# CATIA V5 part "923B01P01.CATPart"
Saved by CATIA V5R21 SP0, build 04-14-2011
Part number: 923B01P01
Bounding box of the stored display mesh (mm): x -17.1 to 17.1, y -76.2 to 76.2, z -4.4 to 4.4
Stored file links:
  C:\Users\ALI OZGUN\Desktop\alhan\923B01P01.CATPart
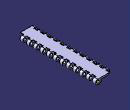
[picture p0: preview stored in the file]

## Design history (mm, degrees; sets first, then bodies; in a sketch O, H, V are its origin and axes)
Body1 (main body)
  Sketch1 on zx-plane, origin (0, 0, 0), H (-1, 0, 0), V (0, 0, 1)
    construction line L1 (-12.7, 0) -> (12.7, 0)
    point P1 (-12.7, 0)
    line L2 (-12.7, 4.4) -> (12.7, 4.4)
    line L3 (12.7, -4.4) -> (-12.7, -4.4)
    arc A1 centre (12.7, 0) radius 4.4 from (12.7, 4.4) to (12.7, -4.4) cw
    arc A2 centre (-12.7, 0) radius 4.4 from (-12.7, -4.4) to (-12.7, 4.4) cw
    distance L1 L2 = 4.4
    length L1 = 25.4
    distance P1 V = 12.7
    coincidence: P1 H
    horizontal: L1 H
    tangency: A1 L2, A2 L2, A1 L3, A2 L3
  Pad1: profile Sketch1, direction (0, 1, 0), length 76.2, mirrored extent
  Sketch2 on face of Pad1 from Sketch1.L2, origin (0, 0, 4.4), H (1, 0, 0), V (0, 1, 0)
    line L1 (-22.3127, -63.5) -> (-9.75, -63.5)
    line L2 (-9.75, -63.5) -> (-9.75, -70.6)
    line L3 (-9.75, -70.6) -> (-22.3127, -70.6)
    line L4 (-22.3127, -70.6) -> (-22.3127, -63.5)
    line L5 (24.6678, -76.95) -> (9.75, -76.95)
    line L6 (9.75, -76.95) -> (9.75, -69.85)
    line L7 (9.75, -69.85) -> (24.6678, -69.85)
    line L8 (24.6678, -69.85) -> (24.6678, -76.95)
    reference projected line E1 (-12.7, -76.2) -> (12.7, -76.2) from edge [start face of Pad1 | face of Pad1 from Sketch1.L2]
    reference projected line E2 (-12.7, -76.2) -> (12.7, -76.2) from edge [start face of Pad1 | face of Pad1 from Sketch1.L2]
    distance L3 E1 = 5.6
    length L4 = 7.1
    distance L7 L5 = 7.1
    distance L5 E2 = 0.75
    distance L2 L6 = 19.5
    distance L2 V = 9.75
    horizontal: L1 H, L3 H, L5 H, L7 H
    vertical: L2 V, L4 V, L6 V, L8 V
  Pocket1: profile Sketch2, direction (0, 0, -1), length 76.2
  RectPattern1: of Pocket1, direction 1 instances 12, spacing 12.7, along axis of face of Pad1 from Sketch1.A2
  Sketch3 on face of Pad1 from Sketch1.L3, origin (0, 0, -4.4), H (1, 0, 0), V (0, -1, 0)
    line L1 (-7, 90.4553) -> (7, 90.4553)
    line L2 (7, 90.4553) -> (7, -88.0088)
    line L3 (7, -88.0088) -> (-7, -88.0088)
    line L4 (-7, -88.0088) -> (-7, 90.4553)
    length L1 = 14
    distance L4 V = 7
    horizontal: L1 H, L3 H
    vertical: L2 V, L4 V
  Pocket2: profile Sketch3, direction (0, 0, 1), length 5.8
  Fillet1: radius 2, on edge [face of Pad1 from Sketch1.L3 | face of Pocket2 from Sketch3.L2]; edge [face of Pad1 from Sketch1.L3 | face of Pocket2 from Sketch3.L4]
  Sketch4 on yz-plane, origin (0, 0, 0), H (0, 1, 0), V (0, 0, 1)
    point P3 (69.85, -4.4)
    point P5 (69.85, -4.4)
    point P7 (57.15, -4.4)
    point P9 (57.15, -4.4)
    point P11 (44.45, -4.4)
    point P13 (44.45, -4.4)
    point P15 (31.75, -4.4)
    point P16 (31.75, -4.4)
    point P18 (19.05, -4.4)
    point P19 (19.05, 1.4)
    point P20 (19.05, -4.4)
    line L1 (-76.2, -4.4) -> (-76.2, 1.4)
    line L2 (-69.85, 1.4) -> (-69.85, -4.4)
    line L3 (-69.85, -4.4) -> (-76.2, -4.4)
    line L4 (-57.15, -4.4) -> (-64.25, -4.4)
    line L5 (-64.25, -4.4) -> (-64.25, 1.4)
    line L6 (-57.15, 1.4) -> (-57.15, -4.4)
    line L7 (-44.45, -4.4) -> (-51.55, -4.4)
    line L8 (-51.55, -4.4) -> (-51.55, 1.4)
    line L9 (-44.45, 1.4) -> (-44.45, -4.4)
    line L10 (-31.75, -4.4) -> (-38.85, -4.4)
    line L11 (-38.85, -4.4) -> (-38.85, 1.4)
    line L12 (-19.05, -4.4) -> (-26.15, -4.4)
    line L13 (-26.15, -4.4) -> (-26.15, 1.4)
    line L14 (-19.05, 1.4) -> (-19.05, -4.4)
    line L15 (-6.35, -4.4) -> (-13.45, -4.4)
    line L16 (-13.45, -4.4) -> (-13.45, 1.4)
    line L17 (-6.35, 1.4) -> (-6.35, -4.4)
    line L18 (6.35, -4.4) -> (-0.75, -4.4)
    line L19 (-0.75, -4.4) -> (-0.75, 1.4)
    line L20 (6.35, 1.4) -> (6.35, -4.4)
    construction line L21 (19.05, -4.4) -> (11.95, -4.4)
    construction line L22 (11.95, -4.4) -> (11.95, 4.4)
    construction line L23 (11.95, 4.4) -> (19.05, 4.4)
    construction line L24 (19.05, 4.4) -> (19.05, -4.4)
    line L25 (19.05, 1.4) -> (19.05, -4.4)
    line L26 (19.05, -4.4) -> (11.95, -4.4)
    line L27 (11.95, -4.4) -> (11.95, 1.4)
    construction line L28 (31.75, -4.4) -> (24.65, -4.4)
    construction line L29 (24.65, -4.4) -> (24.65, 4.4)
    construction line L30 (24.65, 4.4) -> (31.75, 4.4)
    construction line L31 (31.75, 4.4) -> (31.75, -4.4)
    line L32 (31.75, -4.4) -> (24.65, -4.4)
    line L33 (24.65, -4.4) -> (24.65, 1.4)
    line L34 (31.75, 1.4) -> (31.75, -4.4)
    construction line L35 (44.45, -4.4) -> (37.35, -4.4)
    construction line L36 (37.35, -4.4) -> (37.35, 4.4)
    construction line L37 (37.35, 4.4) -> (44.45, 4.4)
    construction line L38 (44.45, 4.4) -> (44.45, -4.4)
    line L39 (44.45, -4.4) -> (37.35, -4.4)
    line L40 (37.35, -4.4) -> (37.35, 1.4)
    line L41 (44.45, 1.4) -> (44.45, -4.4)
    construction line L42 (57.15, -4.4) -> (50.05, -4.4)
    construction line L43 (50.05, -4.4) -> (50.05, 4.4)
    construction line L44 (50.05, 4.4) -> (57.15, 4.4)
    construction line L45 (57.15, 4.4) -> (57.15, -4.4)
    line L46 (57.15, -4.4) -> (50.05, -4.4)
    line L47 (50.05, -4.4) -> (50.05, 1.4)
    line L48 (57.15, 1.4) -> (57.15, -4.4)
    construction line L49 (69.85, -4.4) -> (62.75, -4.4)
    construction line L50 (62.75, -4.4) -> (62.75, 4.4)
    construction line L51 (62.75, 4.4) -> (69.85, 4.4)
    construction line L52 (69.85, 4.4) -> (69.85, -4.4)
    line L53 (69.85, 1.4) -> (69.85, -4.4)
    line L54 (69.85, -4.4) -> (62.75, -4.4)
    line L55 (62.75, -4.4) -> (62.75, 1.4)
    construction line L56 (-76.2, 1.4) -> (76.2, 1.4)
    line L57 (62.75, 1.4) -> (69.85, 1.4)
    line L58 (50.05, 1.4) -> (57.15, 1.4)
    line L59 (37.35, 1.4) -> (44.45, 1.4)
    line L60 (-76.2, 1.4) -> (-69.85, 1.4)
    point P60 (19.05, 1.4)
    line L61 (24.65, 1.4) -> (31.75, 1.4)
    point P61 (24.65, 1.4)
    point P62 (24.65, 1.4)
    point P63 (11.95, 1.4)
    point P64 (6.35, 1.4)
    point P65 (-0.75, 1.4)
    point P66 (-6.35, 1.4)
    point P67 (-13.45, 1.4)
    point P68 (-19.05, 1.4)
    point P69 (-26.15, 1.4)
    point P70 (-38.85, 1.4)
    point P71 (-44.45, 1.4)
    point P72 (-51.55, 1.4)
    point P73 (-57.15, 1.4)
    point P74 (-64.25, 1.4)
    point P75 (-69.85, 1.4)
    line L62 (-64.25, 1.4) -> (-57.15, 1.4)
    line L63 (-51.55, 1.4) -> (-44.45, 1.4)
    line L64 (-38.85, 1.4) -> (-31.75, 1.4)
    line L65 (-26.15, 1.4) -> (-19.05, 1.4)
    line L66 (-13.45, 1.4) -> (-6.35, 1.4)
    line L67 (-0.75, 1.4) -> (6.35, 1.4)
    line L68 (11.95, 1.4) -> (19.05, 1.4)
    line L69 (-31.75, 1.4) -> (-31.75, -4.4)
    coincidence: L24 P60, L29 P61, L60 L61, L56 P62, L56 P63, L56 P64, L56 P65, L56 P66, L56 P67, L56 P68, L56 P69, L56 P70, L56 P71, L56 P72, L56 P73, L56 P74, L56 P75, L60 L62, L62 L63, L63 L64, L64 L65, L65 L66, L66 L67, L67 L68, P3 P5, P7 P9, P11 P13, P15 P16, P18 P20, P19 P60, P61 P62
    vertical: L69 V
  Pocket3: profile Sketch4, direction (1, 0, 0), length 27.8
  Sketch5 on yz-plane, origin (0, 0, 0), H (0, 1, 0), V (0, 0, 1)
    line L1 (-63.5, -4.4) -> (-70.6, -4.4)
    point P1 (-63.5, -4.4)
    point P2 (-70.6, -4.4)
    line L2 (-63.5, 1.4) -> (-63.5, -4.4)
    point P3 (-63.5, 1.4)
    point P4 (-63.5, -4.4)
    line L3 (-70.6, 1.4) -> (-63.5, 1.4)
    point P5 (-70.6, 1.4)
    point P6 (-63.5, 1.4)
    line L4 (-70.6, -4.4) -> (-70.6, 1.4)
    point P7 (-70.6, -4.4)
    point P8 (-70.6, 1.4)
    line L5 (-50.8, 1.4) -> (-50.8, -4.4)
    point P9 (-50.8, 1.4)
    point P10 (-50.8, -4.4)
    line L6 (-57.9, 1.4) -> (-50.8, 1.4)
    point P11 (-57.9, 1.4)
    point P12 (-50.8, 1.4)
    line L7 (-57.9, -4.4) -> (-57.9, 1.4)
    point P13 (-57.9, -4.4)
    point P14 (-57.9, 1.4)
    line L8 (-50.8, -4.4) -> (-57.9, -4.4)
    point P15 (-50.8, -4.4)
    point P16 (-57.9, -4.4)
    line L9 (-38.1, 1.4) -> (-38.1, -4.4)
    point P17 (-38.1, 1.4)
    point P18 (-38.1, -4.4)
    line L10 (-45.2, 1.4) -> (-38.1, 1.4)
    point P19 (-45.2, 1.4)
    point P20 (-38.1, 1.4)
    line L11 (-45.2, -4.4) -> (-45.2, 1.4)
    point P21 (-45.2, -4.4)
    point P22 (-45.2, 1.4)
    line L12 (-38.1, -4.4) -> (-45.2, -4.4)
    point P23 (-38.1, -4.4)
    point P24 (-45.2, -4.4)
    line L13 (-25.4, 1.4) -> (-25.4, -4.4)
    point P25 (-25.4, 1.4)
    point P26 (-25.4, -4.4)
    line L14 (-32.5, 1.4) -> (-25.4, 1.4)
    point P27 (-32.5, 1.4)
    point P28 (-25.4, 1.4)
    line L15 (-32.5, -4.4) -> (-32.5, 1.4)
    point P29 (-32.5, -4.4)
    point P30 (-32.5, 1.4)
    line L16 (-25.4, -4.4) -> (-32.5, -4.4)
    point P31 (-25.4, -4.4)
    point P32 (-32.5, -4.4)
    line L17 (-12.7, 1.4) -> (-12.7, -4.4)
    point P33 (-12.7, 1.4)
    point P34 (-12.7, -4.4)
    line L18 (-19.8, 1.4) -> (-12.7, 1.4)
    point P35 (-19.8, 1.4)
    point P36 (-12.7, 1.4)
    line L19 (-19.8, -4.4) -> (-19.8, 1.4)
    point P37 (-19.8, -4.4)
    point P38 (-19.8, 1.4)
    line L20 (-12.7, -4.4) -> (-19.8, -4.4)
    point P39 (-12.7, -4.4)
    point P40 (-19.8, -4.4)
    line L21 (0, 1.4) -> (0, -4.4)
    point P41 (0, 1.4)
    point P42 (0, -4.4)
    line L22 (-7.1, 1.4) -> (0, 1.4)
    point P43 (-7.1, 1.4)
    point P44 (0, 1.4)
    line L23 (-7.1, -4.4) -> (-7.1, 1.4)
    point P45 (-7.1, -4.4)
    point P46 (-7.1, 1.4)
    line L24 (0, -4.4) -> (-7.1, -4.4)
    point P47 (0, -4.4)
    point P48 (-7.1, -4.4)
    line L25 (12.7, 1.4) -> (12.7, -4.4)
    point P49 (12.7, 1.4)
    point P50 (12.7, -4.4)
    line L26 (5.6, 1.4) -> (12.7, 1.4)
    point P51 (5.6, 1.4)
    point P52 (12.7, 1.4)
    line L27 (5.6, -4.4) -> (5.6, 1.4)
    point P53 (5.6, -4.4)
    point P54 (5.6, 1.4)
    line L28 (12.7, -4.4) -> (5.6, -4.4)
    point P55 (12.7, -4.4)
    point P56 (5.6, -4.4)
    line L29 (18.3, 1.4) -> (25.4, 1.4)
    point P57 (18.3, 1.4)
    point P58 (25.4, 1.4)
    line L30 (18.3, -4.4) -> (18.3, 1.4)
    point P59 (18.3, -4.4)
    point P60 (18.3, 1.4)
    line L31 (25.4, -4.4) -> (18.3, -4.4)
    point P61 (25.4, -4.4)
    point P62 (18.3, -4.4)
    line L32 (25.4, 1.4) -> (25.4, -4.4)
    point P63 (25.4, 1.4)
    point P64 (25.4, -4.4)
    line L33 (38.1, 1.4) -> (38.1, -4.4)
    point P65 (38.1, 1.4)
    point P66 (38.1, -4.4)
    line L34 (31, 1.4) -> (38.1, 1.4)
    point P67 (31, 1.4)
    point P68 (38.1, 1.4)
    line L35 (31, -4.4) -> (31, 1.4)
    point P69 (31, -4.4)
    point P70 (31, 1.4)
    line L36 (38.1, -4.4) -> (31, -4.4)
    point P71 (38.1, -4.4)
    point P72 (31, -4.4)
    line L37 (50.8, 1.4) -> (50.8, -4.4)
    point P73 (50.8, 1.4)
    point P74 (50.8, -4.4)
    line L38 (43.7, 1.4) -> (50.8, 1.4)
    point P75 (43.7, 1.4)
    point P76 (50.8, 1.4)
    line L39 (43.7, -4.4) -> (43.7, 1.4)
    point P77 (43.7, -4.4)
    point P78 (43.7, 1.4)
    line L40 (50.8, -4.4) -> (43.7, -4.4)
    point P79 (50.8, -4.4)
    point P80 (43.7, -4.4)
    line L41 (63.5, 1.4) -> (63.5, -4.4)
    point P81 (63.5, 1.4)
    point P82 (63.5, -4.4)
    line L42 (56.4, 1.4) -> (63.5, 1.4)
    point P83 (56.4, 1.4)
    point P84 (63.5, 1.4)
    line L43 (56.4, -4.4) -> (56.4, 1.4)
    point P85 (56.4, -4.4)
    point P86 (56.4, 1.4)
    line L44 (63.5, -4.4) -> (56.4, -4.4)
    point P87 (63.5, -4.4)
    point P88 (56.4, -4.4)
    line L45 (69.1, 1.4) -> (76.2, 1.4)
    point P89 (69.1, 1.4)
    point P90 (76.2, 1.4)
    line L46 (69.1, -4.4) -> (69.1, 1.4)
    point P91 (69.1, -4.4)
    point P92 (69.1, 1.4)
    line L47 (76.2, -4.4) -> (69.1, -4.4)
    point P93 (76.2, -4.4)
    point P94 (69.1, -4.4)
    line L48 (76.2, 1.4) -> (76.2, -4.4)
    point P95 (76.2, 1.4)
    point P96 (76.2, -4.4)
    distance L4 L2 = 7.1
    coincidence: P96 P93, P95 P90, P94 P91, P92 P89, P88 P85, P87 P82, P86 P83, P84 P81, P80 P77, P79 P74, P78 P75, P76 P73, P72 P69, P71 P66, P70 P67, P68 P65, P64 P61, P63 P58, P62 P59, P60 P57, P56 P53, P55 P50, P54 P51, P52 P49, P48 P45, P47 P42, P46 P43, P44 P41, P40 P37, P39 P34, P38 P35, P36 P33, P32 P29, P31 P26, P30 P27, P28 P25, P24 P21, P23 P18, P22 P19, P20 P17, P16 P13, P15 P10, P14 P11, P12 P9, P8 P5, P7 P2, P6 P3, P4 P1
    fix: L2
  Pocket4: profile Sketch5, direction (-1, 0, 0), length 27.8
  Chamfer1: length 2.5, angle 45, on edge [face of Pocket4 | face of Pocket1 from Sketch2.L6]; edge [face of Pocket4 | face of RectPattern1] (x11); edge [face of RectPattern1 | face of Pocket4] (x11); edge [face of Pocket4 | face of Pocket1 from Sketch2.L2]
  Sketch6 on zx-plane, origin (0, 0, 0), H (-1, 0, 0), V (0, 0, 1)
    circle A1 centre (12.7, 0) radius 2.3
    point P1 (12.7, 0)
    circle A2 centre (-12.7, 0) radius 2.3
    point P2 (-12.7, 0)
    reference projected arc E1 centre (12.7, 0) radius 4.4 from (12.7, -4.4) to (12.7, 4.4) ccw from edge [face of Pocket4 | face of Pad1 from Sketch1.A1]
    reference projected arc E2 centre (-12.7, 0) radius 4.4 from (-12.7, 4.4) to (-12.7, -4.4) ccw from edge [face of Pad1 from Sketch1.A2 | end face of Pad1]
    radius A1 = 2.3
    radius A2 = 2.3
    coincidence: P1 H, P2 H
    concentricity: P1 E1, A2 E2
  Pocket5: profile Sketch6, direction (0, -1, 0), length 97.8, mirrored extent
Body2
  Solid1: linked copy from another document
  Translate1: Direction yz-plane, ToTransfor Solid1, Length 25.4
